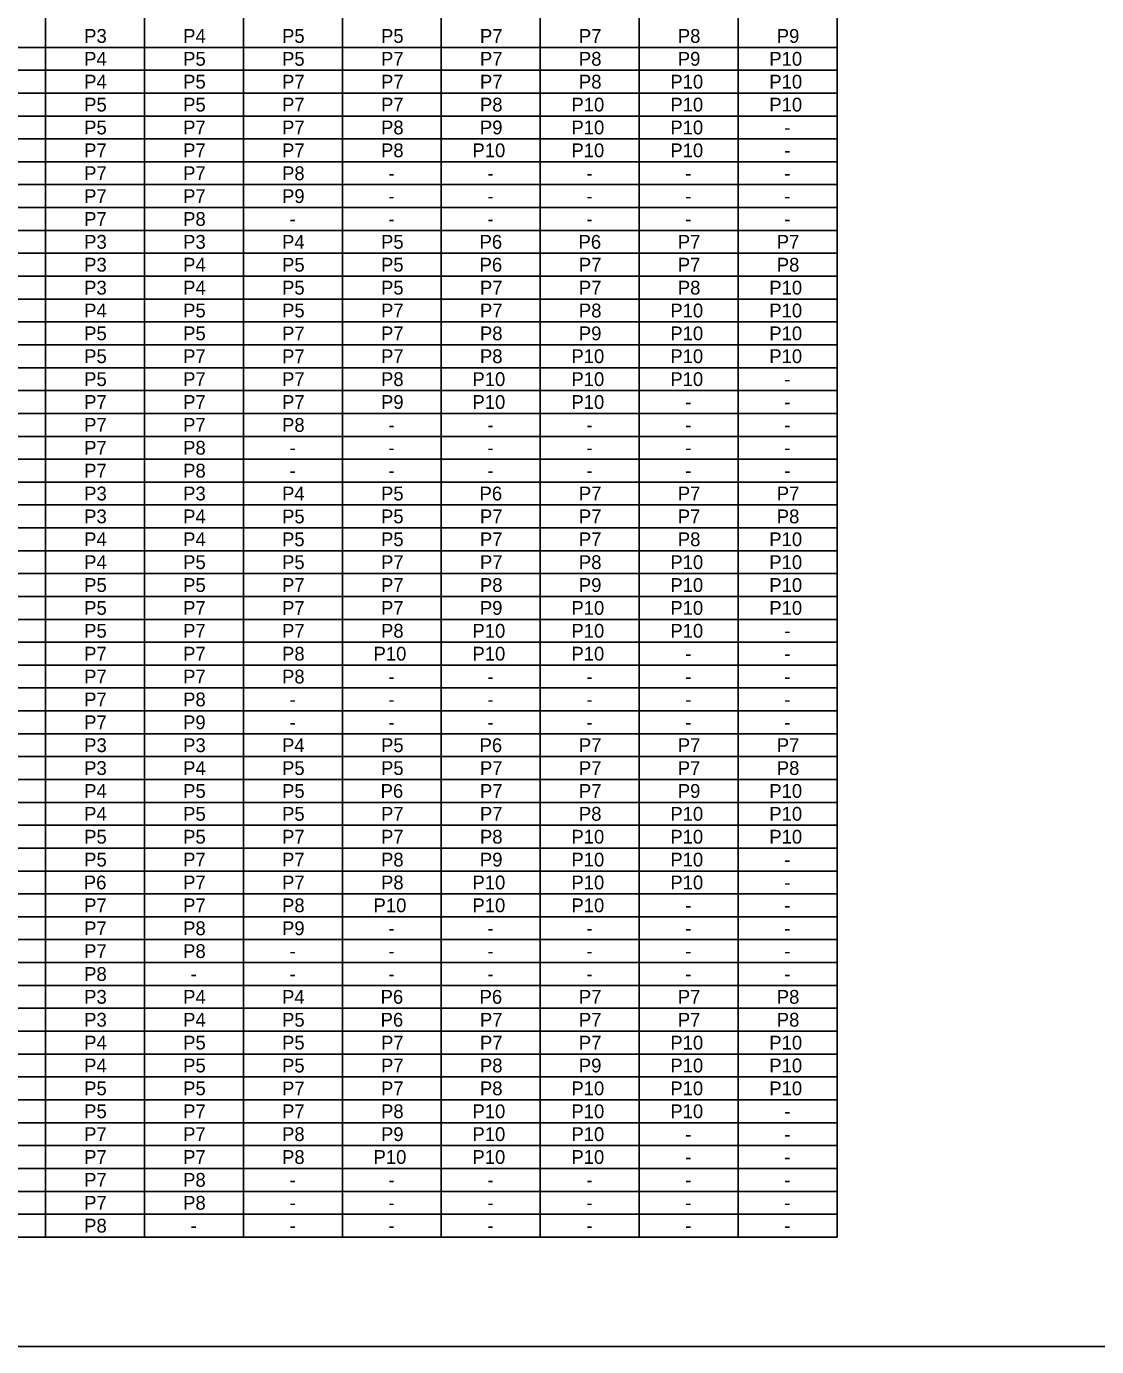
# Model space of a CAD drawing. Extents: x 637580 to 641008, y 294594 to 295782.
# Drawn here: x 640350.4 to 640583.1, y 295202.6 to 295489.6 of the extents above; entities that cross this region are included whole.
import ezdxf

# ---------------------------------------------------------------- set-up
doc = ezdxf.new("R2010")
doc.units = 0
doc.layers.add('1', color=7, linetype='Continuous')
doc.layers.add('2', color=7, linetype='Continuous')

msp = doc.modelspace()

# ---------------------------------------------------------------- linework, layer by layer
at = {"layer": '1'}
for p, q in [((640526.66, 295226.43), (640526.66, 295743.08)), ((640191.43, 295445.22), (640526.66, 295445.22)), ((640191.43, 295390.52), (640526.66, 295390.52)), ((640191.43, 295335.82), (640526.66, 295335.82)), ((640191.43, 295281.12), (640526.66, 295281.12)), ((640191.43, 295226.43), (640526.66, 295226.43)), ((640929.31, 295202.63), (640143.31, 295202.63)), ((640143.31, 295202.63), (640729.31, 295202.63))]:
    msp.add_line(p, q, dxfattribs=at)
at = {"layer": '2'}
for p, q in [((640354.53, 295226.43), (640354.53, 295728.06)), ((640376.05, 295226.43), (640376.05, 295728.06)), ((640397.56, 295226.43), (640397.56, 295728.06)), ((640419.08, 295226.43), (640419.08, 295728.06)), ((640440.6, 295226.43), (640440.6, 295728.06)), ((640462.11, 295226.43), (640462.11, 295728.06)), ((640483.63, 295226.43), (640483.63, 295728.06)), ((640505.14, 295226.43), (640505.14, 295728.06)), ((640218.95, 295485), (640526.66, 295485)), ((640218.95, 295480.02), (640526.66, 295480.02)), ((640218.95, 295475.05), (640526.66, 295475.05)), ((640218.95, 295470.08), (640526.66, 295470.08)), ((640218.95, 295465.11), (640526.66, 295465.11)), ((640218.95, 295460.13), (640526.66, 295460.13)), ((640218.95, 295455.16), (640526.66, 295455.16)), ((640218.95, 295450.19), (640526.66, 295450.19)), ((640218.95, 295440.24), (640526.66, 295440.24)), ((640218.95, 295435.27), (640526.66, 295435.27)), ((640218.95, 295430.3), (640526.66, 295430.3)), ((640218.95, 295425.33), (640526.66, 295425.33)), ((640218.95, 295420.35), (640526.66, 295420.35)), ((640218.95, 295415.38), (640526.66, 295415.38)), ((640218.95, 295410.41), (640526.66, 295410.41)), ((640218.95, 295405.44), (640526.66, 295405.44)), ((640218.95, 295400.46), (640526.66, 295400.46)), ((640218.95, 295395.49), (640526.66, 295395.49)), ((640218.95, 295385.55), (640526.66, 295385.55)), ((640218.95, 295380.57), (640526.66, 295380.57)), ((640218.95, 295375.6), (640526.66, 295375.6)), ((640218.95, 295370.63), (640526.66, 295370.63)), ((640218.95, 295365.66), (640526.66, 295365.66)), ((640218.95, 295360.68), (640526.66, 295360.68)), ((640218.95, 295355.71), (640526.66, 295355.71)), ((640218.95, 295350.74), (640526.66, 295350.74)), ((640218.95, 295345.77), (640526.66, 295345.77)), ((640218.95, 295340.79), (640526.66, 295340.79)), ((640218.95, 295330.85), (640526.66, 295330.85)), ((640218.95, 295325.88), (640526.66, 295325.88)), ((640218.95, 295320.9), (640526.66, 295320.9)), ((640218.95, 295315.93), (640526.66, 295315.93)), ((640218.95, 295310.96), (640526.66, 295310.96)), ((640218.95, 295305.99), (640526.66, 295305.99)), ((640218.95, 295301.01), (640526.66, 295301.01)), ((640218.95, 295296.04), (640526.66, 295296.04)), ((640218.95, 295291.07), (640526.66, 295291.07)), ((640218.95, 295286.1), (640526.66, 295286.1)), ((640218.95, 295276.15), (640526.66, 295276.15)), ((640218.95, 295271.18), (640526.66, 295271.18)), ((640218.95, 295266.21), (640526.66, 295266.21)), ((640218.95, 295261.23), (640526.66, 295261.23)), ((640218.95, 295256.26), (640526.66, 295256.26)), ((640218.95, 295251.29), (640526.66, 295251.29)), ((640218.95, 295246.32), (640526.66, 295246.32)), ((640218.95, 295241.34), (640526.66, 295241.34)), ((640218.95, 295236.37), (640526.66, 295236.37)), ((640218.95, 295231.4), (640526.66, 295231.4))]:
    msp.add_line(p, q, dxfattribs=at)

# ---------------------------------------------------------------- texts
at = {"layer": '1'}
for s, p in [('P3', (640362.94, 295485.98)), ('P4', (640384.46, 295485.98)), ('P5', (640405.97, 295485.98)), ('P5', (640427.49, 295485.98)), ('P7', (640449, 295485.98)), ('P7', (640470.52, 295485.98)), ('P8', (640492.03, 295485.98)), ('P9', (640513.54, 295485.98)), ('P4', (640362.94, 295481.01)), ('P5', (640384.46, 295481.01)), ('P5', (640405.97, 295481)), ('P7', (640427.49, 295481.01)), ('P7', (640449, 295481.01)), ('P8', (640470.52, 295481.01)), ('P9', (640492.02, 295481.01)), ('P10', (640511.92, 295481.01)), ('P4', (640362.94, 295476.04)), ('P5', (640384.46, 295476.04)), ('P7', (640405.97, 295476.03)), ('P7', (640427.49, 295476.04)), ('P7', (640449, 295476.04)), ('P8', (640470.52, 295476.04)), ('P10', (640490.4, 295476.04)), ('P10', (640511.92, 295476.04)), ('P5', (640362.94, 295471.06)), ('P5', (640384.46, 295471.06)), ('P7', (640405.97, 295471.06)), ('P7', (640427.49, 295471.06)), ('P8', (640449, 295471.06)), ('P10', (640468.89, 295471.06)), ('P10', (640490.4, 295471.06)), ('P10', (640511.92, 295471.06)), ('P8', (640427.49, 295466.09)), ('P9', (640448.99, 295466.09)), ('P10', (640468.89, 295466.09)), ('P10', (640490.4, 295466.09)), ('P5', (640362.94, 295466.09)), ('P7', (640384.46, 295466.09)), ('P7', (640405.97, 295466.09)), ('-', (640515.17, 295466.09)), ('P7', (640362.94, 295461.12)), ('P7', (640384.46, 295461.12)), ('P7', (640405.97, 295461.11)), ('P8', (640427.49, 295461.12)), ('P10', (640447.37, 295461.12)), ('P10', (640468.89, 295461.12)), ('P10', (640490.4, 295461.12)), ('-', (640515.17, 295461.12)), ('P7', (640362.94, 295456.15)), ('P7', (640384.46, 295456.15)), ('P8', (640405.97, 295456.14)), ('-', (640429.11, 295456.15)), ('-', (640450.62, 295456.15)), ('-', (640472.14, 295456.15)), ('-', (640493.65, 295456.15)), ('-', (640515.17, 295456.15)), ('P7', (640362.94, 295451.17)), ('P7', (640384.46, 295451.17)), ('P9', (640405.96, 295451.17)), ('-', (640429.11, 295451.17)), ('-', (640450.62, 295451.17)), ('-', (640472.14, 295451.17)), ('-', (640493.65, 295451.17)), ('-', (640515.17, 295451.17)), ('P7', (640362.94, 295446.2)), ('P8', (640384.46, 295446.2)), ('-', (640407.59, 295446.2)), ('-', (640429.11, 295446.2)), ('-', (640450.62, 295446.2)), ('-', (640472.14, 295446.2)), ('-', (640493.65, 295446.2)), ('-', (640515.17, 295446.2)), ('P3', (640362.94, 295441.23)), ('P3', (640384.46, 295441.23)), ('P4', (640405.97, 295441.22)), ('P5', (640427.49, 295441.23)), ('P6', (640448.92, 295441.23)), ('P6', (640470.44, 295441.23)), ('P7', (640492.03, 295441.23)), ('P7', (640513.55, 295441.23)), ('P3', (640362.94, 295436.26)), ('P4', (640384.46, 295436.26)), ('P5', (640405.97, 295436.25)), ('P5', (640427.49, 295436.26)), ('P6', (640448.92, 295436.26)), ('P7', (640470.52, 295436.26)), ('P7', (640492.03, 295436.26)), ('P8', (640513.55, 295436.26)), ('P3', (640362.94, 295431.28)), ('P4', (640384.46, 295431.28)), ('P5', (640405.97, 295431.28)), ('P5', (640427.49, 295431.28)), ('P7', (640449, 295431.28)), ('P7', (640470.52, 295431.28)), ('P8', (640492.03, 295431.28)), ('P10', (640511.92, 295431.28)), ('P4', (640362.94, 295426.31)), ('P5', (640384.46, 295426.31)), ('P5', (640405.97, 295426.31)), ('P7', (640427.49, 295426.31)), ('P7', (640449, 295426.31)), ('P8', (640470.52, 295426.31)), ('P10', (640490.4, 295426.31)), ('P10', (640511.92, 295426.31)), ('P5', (640362.94, 295421.34)), ('P5', (640384.46, 295421.34)), ('P7', (640405.97, 295421.33)), ('P7', (640427.49, 295421.34)), ('P8', (640449, 295421.34)), ('P9', (640470.51, 295421.34)), ('P10', (640490.4, 295421.34)), ('P10', (640511.92, 295421.34)), ('P5', (640362.94, 295416.37)), ('P7', (640384.46, 295416.37)), ('P7', (640405.97, 295416.36)), ('P7', (640427.49, 295416.37)), ('P8', (640449, 295416.37)), ('P10', (640468.89, 295416.37)), ('P10', (640490.4, 295416.37)), ('P10', (640511.92, 295416.37)), ('P5', (640362.94, 295411.39)), ('P7', (640384.46, 295411.39)), ('P7', (640405.97, 295411.39)), ('P8', (640427.49, 295411.39)), ('P10', (640447.37, 295411.39)), ('P10', (640468.89, 295411.39)), ('P10', (640490.4, 295411.39)), ('-', (640515.17, 295411.39)), ('P7', (640362.94, 295406.42)), ('P7', (640384.46, 295406.42)), ('P7', (640405.97, 295406.42)), ('P9', (640427.48, 295406.42)), ('P10', (640447.37, 295406.42)), ('P10', (640468.89, 295406.42)), ('-', (640493.65, 295406.42)), ('-', (640515.17, 295406.42)), ('P7', (640362.94, 295401.45)), ('P7', (640384.46, 295401.45)), ('P8', (640405.97, 295401.44)), ('-', (640429.11, 295401.45)), ('-', (640450.62, 295401.45)), ('-', (640472.14, 295401.45)), ('-', (640493.65, 295401.45)), ('-', (640515.17, 295401.45)), ('P7', (640362.94, 295396.48)), ('P8', (640384.46, 295396.48)), ('-', (640407.59, 295396.47)), ('-', (640429.11, 295396.48)), ('-', (640450.62, 295396.48)), ('-', (640472.14, 295396.48)), ('-', (640493.65, 295396.48)), ('-', (640515.17, 295396.48)), ('P8', (640384.46, 295391.5)), ('P7', (640362.94, 295391.5)), ('-', (640407.59, 295391.5)), ('-', (640429.11, 295391.5)), ('-', (640450.62, 295391.5)), ('-', (640472.14, 295391.5)), ('-', (640493.65, 295391.5)), ('-', (640515.17, 295391.5)), ('P3', (640362.94, 295386.53)), ('P3', (640384.46, 295386.53)), ('P4', (640405.97, 295386.53)), ('P5', (640427.49, 295386.53)), ('P6', (640448.92, 295386.53)), ('P7', (640470.52, 295386.53)), ('P7', (640492.03, 295386.53)), ('P7', (640513.55, 295386.53)), ('P3', (640362.94, 295381.56)), ('P4', (640384.46, 295381.56)), ('P5', (640405.97, 295381.55)), ('P5', (640427.49, 295381.56)), ('P7', (640449, 295381.56)), ('P7', (640470.52, 295381.56)), ('P7', (640492.03, 295381.56)), ('P8', (640513.55, 295381.56)), ('P4', (640362.94, 295376.59)), ('P4', (640384.46, 295376.59)), ('P5', (640405.97, 295376.58)), ('P5', (640427.49, 295376.59)), ('P7', (640449, 295376.59)), ('P7', (640470.52, 295376.59)), ('P8', (640492.03, 295376.59)), ('P10', (640511.92, 295376.59)), ('P4', (640362.94, 295371.61)), ('P5', (640384.46, 295371.61)), ('P5', (640405.97, 295371.61)), ('P7', (640427.49, 295371.61)), ('P7', (640449, 295371.61)), ('P8', (640470.52, 295371.61)), ('P10', (640490.4, 295371.61)), ('P10', (640511.92, 295371.61)), ('P5', (640362.94, 295366.64)), ('P5', (640384.46, 295366.64)), ('P7', (640405.97, 295366.64)), ('P7', (640427.49, 295366.64)), ('P8', (640449, 295366.64)), ('P9', (640470.51, 295366.64)), ('P10', (640490.4, 295366.64)), ('P10', (640511.92, 295366.64)), ('P5', (640362.94, 295361.67)), ('P7', (640384.46, 295361.67)), ('P7', (640405.97, 295361.66)), ('P7', (640427.49, 295361.67)), ('P9', (640448.99, 295361.67)), ('P10', (640468.89, 295361.67)), ('P10', (640490.4, 295361.67)), ('P10', (640511.92, 295361.67)), ('P5', (640362.94, 295356.7)), ('P7', (640384.46, 295356.7)), ('P7', (640405.97, 295356.69)), ('P8', (640427.49, 295356.7)), ('P10', (640447.37, 295356.7)), ('P10', (640468.89, 295356.7)), ('P10', (640490.4, 295356.7)), ('-', (640515.17, 295356.7)), ('P7', (640362.94, 295351.72)), ('P7', (640384.46, 295351.72)), ('P8', (640405.97, 295351.72)), ('P10', (640425.86, 295351.72)), ('P10', (640447.37, 295351.72)), ('P10', (640468.89, 295351.72)), ('-', (640493.65, 295351.72)), ('-', (640515.17, 295351.72)), ('P7', (640362.94, 295346.75)), ('P7', (640384.46, 295346.75)), ('P8', (640405.97, 295346.75)), ('-', (640429.11, 295346.75)), ('-', (640450.62, 295346.75)), ('-', (640472.14, 295346.75)), ('-', (640493.65, 295346.75)), ('-', (640515.17, 295346.75)), ('P7', (640362.94, 295341.78)), ('P8', (640384.46, 295341.78)), ('-', (640407.59, 295341.77)), ('-', (640429.11, 295341.78)), ('-', (640450.62, 295341.78)), ('-', (640472.14, 295341.78)), ('-', (640493.65, 295341.78)), ('-', (640515.17, 295341.78)), ('P7', (640362.94, 295336.81)), ('P9', (640384.44, 295336.81)), ('-', (640407.59, 295336.8)), ('-', (640429.11, 295336.81)), ('-', (640450.62, 295336.81)), ('-', (640472.14, 295336.81)), ('-', (640493.65, 295336.81)), ('-', (640515.17, 295336.81)), ('P3', (640362.94, 295331.83)), ('P3', (640384.46, 295331.83)), ('P4', (640405.97, 295331.83)), ('P5', (640427.49, 295331.83)), ('P6', (640448.92, 295331.83)), ('P7', (640470.52, 295331.83)), ('P7', (640492.03, 295331.83)), ('P7', (640513.55, 295331.83)), ('P3', (640362.94, 295326.86)), ('P4', (640384.46, 295326.86)), ('P5', (640405.97, 295326.86)), ('P5', (640427.49, 295326.86)), ('P7', (640449, 295326.86)), ('P7', (640470.52, 295326.86)), ('P7', (640492.03, 295326.86)), ('P8', (640513.55, 295326.86)), ('P4', (640362.94, 295321.89)), ('P5', (640384.46, 295321.89)), ('P5', (640405.97, 295321.88)), ('P6', (640427.4, 295321.89)), ('P7', (640449, 295321.89)), ('P7', (640470.52, 295321.89)), ('P9', (640492.02, 295321.89)), ('P10', (640511.92, 295321.89)), ('P4', (640362.94, 295316.92)), ('P5', (640384.46, 295316.92)), ('P7', (640427.49, 295316.92)), ('P7', (640449, 295316.92)), ('P8', (640470.52, 295316.92)), ('P10', (640490.4, 295316.92)), ('P10', (640511.92, 295316.92)), ('P5', (640405.97, 295316.91)), ('P5', (640362.94, 295311.94)), ('P5', (640384.46, 295311.94)), ('P7', (640405.97, 295311.94)), ('P7', (640427.49, 295311.94)), ('P8', (640449, 295311.94)), ('P10', (640468.89, 295311.94)), ('P10', (640490.4, 295311.94)), ('P10', (640511.92, 295311.94)), ('P5', (640362.94, 295306.97)), ('P7', (640384.46, 295306.97)), ('P7', (640405.97, 295306.97)), ('P8', (640427.49, 295306.97)), ('P9', (640448.99, 295306.97)), ('P10', (640468.89, 295306.97)), ('P10', (640490.4, 295306.97)), ('-', (640515.17, 295306.97)), ('P6', (640362.86, 295302)), ('P7', (640384.46, 295302)), ('P7', (640405.97, 295301.99)), ('P8', (640427.49, 295302)), ('P10', (640447.37, 295302)), ('P10', (640468.89, 295302)), ('P10', (640490.4, 295302)), ('-', (640515.17, 295302)), ('P7', (640362.94, 295297.03)), ('P7', (640384.46, 295297.03)), ('P8', (640405.97, 295297.02)), ('P10', (640425.86, 295297.03)), ('P10', (640447.37, 295297.03)), ('P10', (640468.89, 295297.03)), ('-', (640493.65, 295297.03)), ('-', (640515.17, 295297.03)), ('P7', (640362.94, 295292.05)), ('P8', (640384.46, 295292.05)), ('P9', (640405.96, 295292.05)), ('-', (640429.11, 295292.05)), ('-', (640450.62, 295292.05)), ('-', (640472.14, 295292.05)), ('-', (640493.65, 295292.05)), ('-', (640515.17, 295292.05)), ('P7', (640362.94, 295287.08)), ('P8', (640384.46, 295287.08)), ('-', (640407.59, 295287.08)), ('-', (640429.11, 295287.08)), ('-', (640450.62, 295287.08)), ('-', (640472.14, 295287.08)), ('-', (640493.65, 295287.08)), ('-', (640515.17, 295287.08)), ('P8', (640362.94, 295282.11)), ('-', (640386.07, 295282.11)), ('-', (640407.59, 295282.1)), ('-', (640429.11, 295282.11)), ('-', (640450.62, 295282.11)), ('-', (640472.14, 295282.11)), ('-', (640493.65, 295282.11)), ('-', (640515.17, 295282.11)), ('P3', (640362.94, 295277.14)), ('P4', (640384.46, 295277.14)), ('P4', (640405.97, 295277.13)), ('P6', (640427.4, 295277.14)), ('P6', (640448.92, 295277.14)), ('P7', (640470.52, 295277.14)), ('P7', (640492.03, 295277.14)), ('P8', (640513.55, 295277.14)), ('P3', (640362.94, 295272.16)), ('P4', (640384.46, 295272.16)), ('P5', (640405.97, 295272.16)), ('P6', (640427.4, 295272.16)), ('P7', (640449, 295272.16)), ('P7', (640470.52, 295272.16)), ('P7', (640492.03, 295272.16)), ('P8', (640513.55, 295272.16)), ('P4', (640362.94, 295267.19)), ('P5', (640384.46, 295267.19)), ('P5', (640405.97, 295267.19)), ('P7', (640427.49, 295267.19)), ('P7', (640449, 295267.19)), ('P7', (640470.52, 295267.19)), ('P10', (640490.4, 295267.19)), ('P10', (640511.92, 295267.19)), ('P4', (640362.94, 295262.22)), ('P5', (640384.46, 295262.22)), ('P5', (640405.97, 295262.21)), ('P7', (640427.49, 295262.22)), ('P8', (640449, 295262.22)), ('P9', (640470.51, 295262.22)), ('P10', (640490.4, 295262.22)), ('P10', (640511.92, 295262.22)), ('P5', (640362.94, 295257.25)), ('P5', (640384.46, 295257.25)), ('P7', (640405.97, 295257.24)), ('P7', (640427.49, 295257.25)), ('P8', (640449, 295257.25)), ('P10', (640468.89, 295257.25)), ('P10', (640490.4, 295257.25)), ('P10', (640511.92, 295257.25)), ('P5', (640362.94, 295252.27)), ('P7', (640384.46, 295252.27)), ('P7', (640405.97, 295252.27)), ('P8', (640427.49, 295252.27)), ('P10', (640447.37, 295252.27)), ('P10', (640468.89, 295252.27)), ('P10', (640490.4, 295252.27)), ('-', (640515.17, 295252.27)), ('P7', (640362.94, 295247.3)), ('P7', (640384.46, 295247.3)), ('P8', (640405.97, 295247.3)), ('P9', (640427.48, 295247.3)), ('P10', (640447.37, 295247.3)), ('P10', (640468.89, 295247.3)), ('-', (640493.65, 295247.3)), ('-', (640515.17, 295247.3)), ('P7', (640362.94, 295242.33)), ('P7', (640384.46, 295242.33)), ('P8', (640405.97, 295242.32)), ('P10', (640425.86, 295242.33)), ('P10', (640447.37, 295242.33)), ('P10', (640468.89, 295242.33)), ('-', (640493.65, 295242.33)), ('-', (640515.17, 295242.33)), ('P7', (640362.94, 295237.36)), ('P8', (640384.46, 295237.36)), ('-', (640407.59, 295237.35)), ('-', (640429.11, 295237.36)), ('-', (640450.62, 295237.36)), ('-', (640472.14, 295237.36)), ('-', (640493.65, 295237.36)), ('-', (640515.17, 295237.36)), ('P7', (640362.94, 295232.38)), ('P8', (640384.46, 295232.38)), ('-', (640407.59, 295232.38)), ('-', (640429.11, 295232.38)), ('-', (640450.62, 295232.38)), ('-', (640472.14, 295232.38)), ('-', (640493.65, 295232.38)), ('-', (640515.17, 295232.38)), ('P8', (640362.94, 295227.41)), ('-', (640386.07, 295227.41)), ('-', (640407.59, 295227.41)), ('-', (640429.11, 295227.41)), ('-', (640450.62, 295227.41)), ('-', (640472.14, 295227.41)), ('-', (640493.65, 295227.41)), ('-', (640515.17, 295227.41))]:
    msp.add_text(s, height=3, dxfattribs=at).set_placement(p)

doc.saveas('drawing.dxf')
